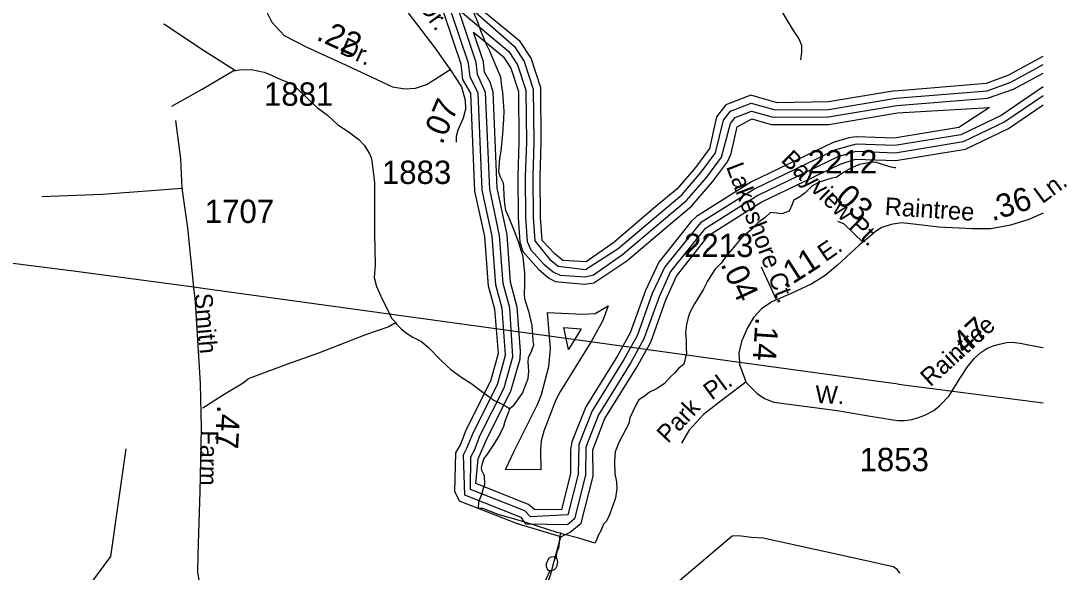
# Model space of a CAD drawing. Extents: x 2315291 to 2336543, y 597177 to 615230.
# Drawn here: x 2330575 to 2336179, y 606314 to 609266 of the extents above; entities that cross this region are included whole.
import ezdxf

# ---------------------------------------------------------------- set-up
doc = ezdxf.new("R2010")
doc.units = 0
for name, color, linetype in [('Exist Hydrographic Buffer Line', 7, 'Continuous'), ('Exist Hydrographic Creek Single Shore', 7, 'Continuous'), ('Exist Hydrographic Lake Shore', 7, 'Continuous'), ('Exist Hydrographic Misc Water Feature', 7, 'Continuous'), ('Exist Road Non-System Type 51', 7, 'Continuous'), ('Exist Road Non-System Type 51 Label', 7, 'Continuous'), ('Exist Road Secondary Mileage Hundredths English Label', 7, 'Continuous'), ('Exist Road Secondary Type 51 Attributed', 7, 'Continuous'), ('Exist Road Secondary Type 51 Label', 7, 'Continuous'), ('Exist Road Secondary Type 51 Number Label', 7, 'Continuous'), ('Exist Utilities Electrical Transmission Line', 7, 'Continuous')]:
    doc.layers.add(name, color=color, linetype=linetype)

msp = doc.modelspace()

# ---------------------------------------------------------------- linework, layer by layer
at = {"layer": 'Exist Hydrographic Buffer Line'}
for points in [[(2333503.2, 606568), (2333282.1, 606570.3), (2333254.4, 606606.8), (2332953.6, 606725.7), (2332945.2, 606941.9), (2332964.5, 606977.1), (2332998.9, 607063.3), (2333128.1, 607319.6), (2333171.2, 607476.6), (2333153.1, 607725.6), (2333118.9, 607852.7), (2333099.4, 608113.8), (2333046.1, 608359.9), (2333024.4, 608880.6), (2332981.1, 608965.3), (2332973.1, 609038.8), (2332835.9, 609447.4)], [(2332939.7, 609372.8), (2333218.3, 609128.4), (2333271.3, 609048.4), (2333319.4, 608900.7), (2333322.5, 608615.7), (2333316.4, 608432.6), (2333318.4, 608214.4), (2333327.4, 608087.6), (2333406.2, 607990.4), (2333452.1, 607952.3), (2333600, 607935.2), (2333774.4, 608046.9), (2333991.2, 608231.7), (2334115.2, 608335.1), (2334219, 608455.4), (2334294.7, 608559.2), (2334338.5, 608734.2), (2334376.3, 608782.8), (2334486.4, 608825.3), (2334615.4, 608788.7), (2334901.2, 608791.8), (2335261.5, 608852.3), (2335749.7, 608891.7), (2335876.6, 608938.3), (2336050.3, 609032.2)], [(2333304.9, 606610), (2333274.5, 606641.5), (2332982.7, 606757.2), (2332985, 606931), (2333003.9, 606966.9), (2333035.4, 607046.9), (2333164, 607301.6), (2333209.7, 607466.2), (2333193.1, 607728.9), (2333158.7, 607859.5), (2333139.2, 608116.8), (2333086.3, 608365), (2333064.4, 608882.3), (2333020.3, 608977.9), (2333012.9, 609043.1), (2332918.8, 609326.2), (2333188.2, 609101.3), (2333234.8, 609030.8), (2333279.7, 608894), (2333282.5, 608616.2), (2333276.4, 608433.9), (2333278.4, 608214), (2333287.7, 608084.7), (2333306.1, 608039), (2333376.9, 607963.1), (2333426.7, 607921.4), (2333463.4, 607904.4), (2333597.3, 607895.4), (2333642.4, 607905.9), (2333797.4, 608014.2), (2334017, 608201.1), (2334140.7, 608304.3), (2334249.1, 608429.3), (2334327.3, 608535.6), (2334375.5, 608716.5), (2334400.9, 608749.4), (2334488.4, 608783.1), (2334604.7, 608750.2), (2334901.6, 608751.8), (2335266.4, 608812.7), (2335753, 608851.8), (2335891, 608900.8), (2336050.3, 608986.8)], [(2333469.9, 606648.4), (2333325.8, 606649.9), (2333294.4, 606676.1), (2333011.9, 606788.7), (2333024.4, 606920.2), (2333071.9, 607030.5), (2333199.7, 607283.6), (2333248.5, 607455.9), (2333252, 607496.6), (2333232.9, 607732.1), (2333198.3, 607866.4), (2333179.2, 608119.8), (2333125.9, 608370.2), (2333104.3, 608884), (2333088.8, 608938.4), (2333059, 608990.5), (2333052.7, 609047.5), (2333000.2, 609204.8), (2333158.3, 609074.4), (2333198.5, 609013.3), (2333239.7, 608887.4), (2333242.5, 608616.6), (2333236.4, 608435.2), (2333238.4, 608213.6), (2333247.7, 608081.7), (2333263.5, 608030.4), (2333347.7, 607935.8), (2333401.5, 607890.4), (2333436.5, 607870.5), (2333594.6, 607855.5), (2333643.4, 607862.4), (2333820.4, 607981.5), (2334042.9, 608170.6), (2334166.5, 608273.6), (2334279.7, 608403.3), (2334359.5, 608512), (2334379.6, 608555.8), (2334412.4, 608699), (2334490.3, 608741), (2334593.6, 608711.8), (2334902.4, 608711.8), (2335271.1, 608772.9), (2335762.2, 608802.9), (2335598, 608694.9), (2335253.3, 608638.6), (2335049.7, 608645.8), (2335009.3, 608640.2), (2334926.2, 608613.9), (2334488.2, 608403.4), (2334194.2, 608218), (2334164.5, 608191.2), (2333992.4, 607974.2), (2333920, 607821.7), (2333838.6, 607595.7), (2333771, 607472.7), (2333600.8, 607199.3), (2333526.5, 607012.2), (2333518.5, 606969.2), (2333519.4, 606842.7), (2333469.9, 606648.4)], [(2336050.3, 608912), (2335825.4, 608759.9), (2335610.3, 608656.4), (2335255.7, 608598.5), (2335048.2, 608605.8), (2334938.1, 608575.8), (2334505.7, 608367.4), (2334215.7, 608184.2), (2334023.8, 607949.3), (2333956.5, 607805.4), (2333875.1, 607579.2), (2333805.4, 607452.4), (2333634.4, 607178.2), (2333563.7, 606997.9), (2333559.6, 606837.9), (2333504.2, 606621), (2333304.9, 606610)], [(2336050.3, 608863.9), (2335845.5, 608725), (2335622.2, 608617.8), (2335258.2, 608558.4), (2335047, 608565.8), (2334950.4, 608537.6), (2334522.9, 608331.4), (2334237, 608150.4), (2334055.2, 607924.5), (2333993, 607789), (2333912, 607562.7), (2333839.9, 607432.2), (2333668.4, 607157), (2333601.2, 606983.5), (2333599.5, 606833), (2333539.9, 606598.6), (2333503.2, 606568)], [(2333359.2, 606862.1), (2333171.4, 606862.9), (2333218.1, 606964.9), (2333342.4, 607211.6), (2333362.9, 607265.2), (2333402.9, 607414.5), (2333411.5, 607509.4), (2333395.7, 607704.8), (2333584.4, 607695.7), (2333651, 607699.4), (2333720.9, 607740.4), (2333692.4, 607661.7), (2333633, 607553.6), (2333464.6, 607283.9), (2333441, 607236.3), (2333376.9, 607069.6), (2333362.7, 607017.8), (2333358.4, 606969.2), (2333359.2, 606862.1)], [(2333508.3, 607505.5), (2333482.5, 607623.5), (2333576, 607616.2), (2333508.3, 607505.5)]]:
    msp.add_lwpolyline(points, dxfattribs=at)
at = {"layer": 'Exist Hydrographic Creek Single Shore'}
msp.add_lwpolyline([(2331553.5, 602566.1), (2331594.5, 602617), (2331766.4, 602893.1), (2332166.4, 603621.4), (2332288.4, 603905.2), (2332508.5, 604324.4), (2333168.2, 605058.9), (2333228.5, 605153.4), (2333244.6, 605266.1), (2333246.6, 605470.2), (2333248.1, 605841.5), (2333262.7, 605910.9), (2333411.5, 606298.5), (2333429.6, 606364.9), (2333467.8, 606503.8)], dxfattribs=at)
at = {"layer": 'Exist Hydrographic Lake Shore'}
for points in [[(2333467.8, 606503.8), (2333234.5, 606572.2), (2332924.5, 606694.2), (2332899.5, 606745.7), (2332905.4, 606952.7), (2332929.4, 606996.3), (2332962.4, 607079.7), (2333092.4, 607337.6), (2333132.4, 607486.9), (2333113.4, 607722.4), (2333079.5, 607845.8), (2333059.4, 608110.8), (2333006.5, 608354.8), (2332984.4, 608878.9), (2332942.3, 608952.7), (2332933.5, 609034.4), (2332795.5, 609442.3), (2332802.5, 609534.5), (2332819.5, 609558.1), (2332944.4, 609543.5)], [(2335256.6, 608892.1), (2334900.4, 608831.8), (2334626.4, 608827.2), (2334484.5, 608867.4), (2334351.5, 608816.1), (2334301.4, 608751.7), (2334262.5, 608582.8), (2334188.5, 608481.3), (2334089.4, 608365.8), (2333965.6, 608262.2), (2333751.5, 608079.7), (2333602.4, 607975.2), (2333477.5, 607983.3), (2333435.5, 608017.7), (2333367.4, 608090.5), (2333358.4, 608214.8), (2333356.3, 608431.3), (2333362.5, 608615.3), (2333359.4, 608907.2), (2333307.5, 609065.9), (2333248.5, 609155.4), (2332979.5, 609377.5)], [(2335256.6, 608892.1), (2335746.4, 608931.6), (2335862.5, 608975.7), (2336050.3, 609077.5)], [(2335260.7, 608518.3), (2335634.5, 608579.2), (2335865.6, 608690.3), (2336050.3, 608815.5)], [(2333467.8, 606503.8), (2333517.5, 606527.9), (2333575.5, 606576.1), (2333639.5, 606828.1), (2333638.5, 606969.2), (2333702.5, 607135.9), (2333874.5, 607411.9), (2333948.5, 607546.2), (2334029.5, 607772.6), (2334086.5, 607899.7), (2334258.4, 608116.7), (2334540.5, 608295.4), (2334962.5, 608499.5), (2335045.6, 608525.8), (2335260.7, 608518.3)]]:
    msp.add_lwpolyline(points, dxfattribs=at)
at = {"layer": 'Exist Hydrographic Misc Water Feature'}
for points in [[(2333194.4, 607187.6), (2333198.3, 607193.5), (2333217.9, 607210), (2333231.9, 607229.8), (2333261.6, 607272.4), (2333279, 607318.4), (2333292.4, 607350.4), (2333296.1, 607390.5), (2333294.2, 607414.7), (2333291.8, 607438.6), (2333293.6, 607462.6), (2333311, 607500.5), (2333322.7, 607530.8), (2333318.2, 607554.6), (2333313.3, 607634.4), (2333296.9, 607704.2), (2333276, 607770.2), (2333271.7, 607796), (2333275.1, 607859.9), (2333274.7, 607916), (2333269.8, 607965.8), (2333265.5, 608001.7), (2333238.6, 608087.7), (2333218.3, 608139.4), (2333189.2, 608214.7), (2333173.2, 608250.8), (2333166.5, 608286.7), (2333164.2, 608330.4), (2333161.8, 608376.6), (2333159.5, 608396.5), (2333142.9, 608432.2), (2333134.5, 608458.2), (2333140.2, 608530.4), (2333147.4, 608568.2), (2333156.2, 608660.5), (2333162, 608740.4), (2333163, 608782.4), (2333160.7, 608832.2), (2333156.2, 608884.4), (2333151.7, 608914.3), (2333145.1, 608964.3), (2333122.8, 609018), (2333087.7, 609103.6), (2333065.6, 609147), (2333038.7, 609212.7), (2333022.1, 609258.6), (2332978.8, 609366.1)], [(2331341.1, 609250.8), (2331558.7, 609104.9), (2331725.4, 609000.7)], [(2331383.7, 608809.2), (2331547, 608901), (2331711.4, 608998.7), (2331725.4, 609000.7)], [(2331725.4, 609000.7), (2331743.6, 609003.3), (2331809.6, 609005.9), (2331877.5, 608990.4), (2331921.4, 608972.9), (2331971.8, 608949.4), (2332028.2, 608928), (2332064.7, 608894.5), (2332112.9, 608849.2), (2332163.4, 608799.8), (2332217.9, 608760.3), (2332272.2, 608708.8), (2332328.8, 608673.5), (2332385.4, 608630.1), (2332415.8, 608598.4), (2332442.2, 608554.6), (2332453.9, 608529), (2332469.7, 608401.3), (2332468.7, 608127.3), (2332472.2, 607959.3), (2332467.4, 607891.5), (2332479.8, 607843.4), (2332512.6, 607771.9), (2332545.4, 607706.1), (2332559.5, 607674.4), (2332579.6, 607654.8), (2332581.7, 607650.8)], [(2335261.3, 608479.2), (2335253.7, 608479.2), (2335235.7, 608482.7), (2335195.5, 608494.5), (2335169, 608504.1), (2335155.1, 608509.8), (2335123.3, 608507.7), (2335067.5, 608497.1), (2335023.2, 608478.6), (2334985.9, 608458.3), (2334959.9, 608439.9), (2334942.2, 608427.9), (2334918, 608423.5), (2334884, 608413.2), (2334846.7, 608400.6), (2334811, 608380.4), (2334775.5, 608346), (2334747.6, 608323.8), (2334714, 608303.3), (2334706, 608283), (2334690.2, 608247.2), (2334650.4, 608232.6), (2334622.5, 608236.4), (2334590.4, 608239.9), (2334562.7, 608215.7), (2334522.7, 608185.2), (2334483.3, 608142.9), (2334451.5, 608118.5), (2334418.3, 608084.2), (2334382.4, 608041.7), (2334352.9, 608005.6), (2334325.2, 607969.2), (2334291.8, 607934.9), (2334252.6, 607872.7), (2334230.9, 607828.5), (2334205.5, 607788.1), (2334183.7, 607750), (2334158.1, 607703.6), (2334148.7, 607677.4), (2334140.7, 607639.3), (2334135.5, 607597.5), (2334137.8, 607555.4), (2334138.6, 607511.4), (2334140.7, 607485.6), (2334133.1, 607457.6), (2334125.5, 607427.5), (2334099.5, 607407), (2334077.7, 607381.1), (2334058, 607362.6), (2334036.1, 607340.3), (2334022.6, 607324.5), (2333982.8, 607298.1), (2333942.8, 607277.3), (2333913.1, 607255), (2333885.4, 607236.9), (2333871.6, 607215), (2333852.2, 607174.5), (2333836.4, 607140.5), (2333830.8, 607110.5), (2333813.2, 607076.2), (2333797.2, 607046.2), (2333778.1, 607007.7), (2333758.3, 606957.6), (2333755.2, 606905.7), (2333755.6, 606839.9), (2333766, 606797.8), (2333766.7, 606760), (2333759.5, 606711.6), (2333743.7, 606665.7), (2333724, 606611.5), (2333710.5, 606585.6), (2333696.5, 606571.4), (2333681.2, 606535.2), (2333665.4, 606506.8), (2333658, 606484.8), (2333649.8, 606469), (2333563.2, 606495.8), (2333479.2, 606516.9), (2333465.2, 606522.7)], [(2331549.2, 607193.8), (2331664.3, 607266.9), (2331765.3, 607327.9), (2331795.1, 607350.2), (2332004.4, 607428.7), (2332171.6, 607488.2), (2332422.3, 607587.2), (2332541.7, 607628.4), (2332581.7, 607650.8)], [(2332581.7, 607650.8), (2332587.6, 607641), (2332612, 607617), (2332640.1, 607593.4), (2332674.1, 607571.6), (2332720.5, 607548.4), (2332760.9, 607514.8), (2332819.7, 607455.2), (2332857.7, 607417.8), (2332878.4, 607398.2), (2332936.4, 607356.5), (2332985.2, 607325.3), (2333035.4, 607287.7), (2333069.7, 607264.3), (2333108.2, 607234.6), (2333146.2, 607217.1), (2333172.2, 607203.5), (2333184.1, 607195.6), (2333194.4, 607187.6)], [(2333465.2, 606522.7), (2333453.3, 606524.5), (2333330.9, 606563.2), (2333238.4, 606592.5), (2333132.2, 606623.1), (2333050.2, 606654.1), (2333026, 606654.1), (2333027.9, 606689.9), (2333045.3, 606736.4), (2333052.9, 606764.4), (2333060.5, 606784.3), (2333058.4, 606830.1), (2333043.8, 606858.2), (2333041.8, 606871.9), (2333047.5, 606896.1), (2333055.1, 606920.2), (2333070.7, 606940.5), (2333084.7, 606962.4), (2333110.5, 606998.6), (2333135.9, 607041.1), (2333161.5, 607095.2), (2333168.7, 607123.3), (2333184.7, 607163.5), (2333194.4, 607187.6)], [(2331137.9, 606973.4), (2331096.5, 606687.2), (2331055.9, 606396.9), (2330906.2, 606197.6), (2330770, 606020.2), (2330696.6, 605757.5), (2330592.7, 605410.6), (2330575.4, 605328.4), (2330556.2, 605266), (2330553.1, 605195.9), (2330551.6, 605144.3), (2330560.3, 605086.2), (2330564.8, 605034.4), (2330575.4, 604982.5), (2330583.6, 604940.7), (2330595.9, 604904.8), (2330596.3, 604886.9), (2330592.7, 604848.9), (2330557.4, 604752.5), (2330493.2, 604629.9), (2330403.4, 604428.9), (2330321.2, 604254.3), (2330246.9, 604099.6)], [(2335284.9, 606308.6), (2335280.8, 606312.4), (2335268.5, 606328), (2335248.8, 606342), (2335224.2, 606347.7), (2334957.8, 606406.8), (2334551, 606496.4), (2334489.1, 606499.6), (2334418.9, 606509), (2334384.9, 606506.8), (2334161, 606318.2), (2333830.4, 606037.1), (2333614.3, 605852.6), (2333402.5, 605866.3), (2333240.7, 605874.8)], [(2333465.2, 606522.7), (2333459.5, 606500.8), (2333457.8, 606470.7), (2333454.2, 606442.9), (2333446.6, 606422.5), (2333442.9, 606402.8), (2333442.7, 606388.6)], [(2333407.4, 606320.1), (2333403.5, 606320.3), (2333395.5, 606330), (2333391, 606342), (2333391, 606359.9), (2333396.7, 606376.1), (2333402.5, 606388.2), (2333415, 606396.4), (2333426.7, 606398.3), (2333432.4, 606396.6), (2333442.7, 606388.6)], [(2333442.7, 606388.6), (2333446.6, 606384.8), (2333449, 606366.5), (2333447.4, 606358.7), (2333443.5, 606342.7), (2333439.6, 606334.8), (2333429.3, 606324.5), (2333417.7, 606320.2), (2333407.4, 606320.1)], [(2333407.4, 606320.1), (2333388.1, 606278), (2333372.3, 606252), (2333364.8, 606219.9), (2333345.1, 606165.6), (2333323.5, 606115.4), (2333300.6, 606043.4), (2333281.3, 605989.1), (2333256.1, 605918.7), (2333242.5, 605880.6), (2333240.7, 605874.8)]]:
    msp.add_lwpolyline(points, dxfattribs=at)
at = {"layer": 'Exist Road Non-System Type 51'}
for points in [[(2333859.1, 610753.3), (2333871.9, 610668.6), (2333880.2, 610611.9), (2333895.2, 610572.7), (2334063.6, 610303.3), (2334625.4, 609357.4), (2334712.1, 609213.9), (2334742.1, 609170.6), (2334755.4, 609135.5), (2334755.4, 609097.2), (2334751, 609057.7)], [(2331439.6, 608370.6), (2331432, 608526.5), (2331405.4, 608731.9)], [(2330687, 608325), (2331012, 608338.3), (2331439.6, 608370.6)], [(2334458.7, 607330.6), (2334349.7, 607249.7), (2334231.3, 607158.2), (2334152.8, 607072.6), (2334112.7, 607004.2)]]:
    msp.add_lwpolyline(points, dxfattribs=at)
at = {"layer": 'Exist Road Secondary Type 51 Attributed'}
msp.add_line((2334622.2, 607771.9), (2334541.9, 607947.7), dxfattribs=at)
for points in [[(2331866.3, 609593.5), (2331953, 609631.8), (2332024.7, 609643.5), (2332084.7, 609638.5), (2332171.4, 609615.1), (2332373.1, 609521.7), (2332476.5, 609466.7), (2332554.9, 609423.3), (2332594.9, 609389.9), (2332653.2, 609304), (2332791.6, 609121.4), (2332860.2, 609025.7), (2332874.9, 609006.3)], [(2331883, 609329.9), (2331919.7, 609259.8), (2331984.7, 609188.1), (2332106.4, 609124.7), (2332313.1, 609031.3), (2332564.9, 608912.8), (2332631.5, 608902.8), (2332688.2, 608906.2), (2332748.2, 608924.5), (2332793.3, 608952.9), (2332874.9, 609006.3)], [(2332874.9, 609006.3), (2332935, 608912.8), (2332955, 608841.1), (2332956.6, 608792.7), (2332943.3, 608744.4), (2332915, 608681), (2332906.6, 608645.9), (2332906.6, 608615.9)], [(2331707.5, 605814.9), (2331641.9, 605953.7), (2331570.7, 606114.4), (2331540.3, 606203.8), (2331523.2, 606316), (2331525.1, 606405.4), (2331528.9, 606525.2), (2331534.6, 606745.7), (2331542.2, 607085.2), (2331537.2, 607323.8), (2331509.9, 607762.1), (2331502, 607839.9), (2331470, 608157.6), (2331439.6, 608370.6)], [(2336050.3, 608236.5), (2335973.8, 608202.4), (2335875.4, 608171.9), (2335769.9, 608152), (2335672.7, 608152), (2335492.2, 608161.9), (2335372.7, 608174.8), (2335291.8, 608184.2), (2335236.8, 608174.8), (2335186.4, 608159.6), (2335157.1, 608140.8), (2335112.6, 608103.3), (2335084.2, 608080.4)], [(2335084.2, 608080.4), (2334982.6, 608179.3), (2334950.5, 608192.2)], [(2335084.2, 608080.4), (2335064.5, 608064.6), (2334949.1, 607957.4), (2334882.9, 607902.2), (2334811.4, 607857.6), (2334701.2, 607806.1), (2334622.2, 607771.9)], [(2334622.2, 607771.9), (2334598.1, 607761.5), (2334541.9, 607724), (2334498.5, 607678.2), (2334466.9, 607622), (2334435.2, 607549.3), (2334421.2, 607488.3), (2334424, 607437), (2334424.7, 607425), (2334448.2, 607358.3), (2334458.7, 607330.6), (2334517.8, 607271.2), (2334557.5, 607243), (2334607.5, 607223.9)], [(2334607.5, 607223.9), (2334947.2, 607180), (2335114.1, 607150.2), (2335247.5, 607128.7), (2335275.5, 607126.6), (2335309.9, 607126.6), (2335346.4, 607130.9), (2335376.6, 607139.5), (2335417.4, 607154.5), (2335464.8, 607180.3), (2335497, 607206.1), (2335546.5, 607257.7), (2335604.6, 607350.2), (2335644.7, 607412.9), (2335683.3, 607459.4), (2335717.3, 607490), (2335749.1, 607511.6), (2335782, 607525.2), (2335816.1, 607535.4), (2335854.7, 607543.4), (2335885.3, 607546), (2335926.9, 607540.3), (2336035.7, 607519.4), (2336050.3, 607516.7)]]:
    msp.add_lwpolyline(points, dxfattribs=at)
at = {"layer": 'Exist Utilities Electrical Transmission Line'}
for p, q in [((2335273.5, 607320.2), (2334424, 607437)), ((2336050.3, 607219.6), (2335275.4, 607319.6))]:
    msp.add_line(p, q, dxfattribs=at)
for points in [[(2331502, 607839.9), (2330843.2, 607928.1), (2329978.4, 608036.7), (2329107.7, 608149.3), (2329014.6, 608160.7)], [(2334424, 607437), (2333818, 607520.3), (2331561.9, 607831.9), (2331502, 607839.9)]]:
    msp.add_lwpolyline(points, dxfattribs=at)

# ---------------------------------------------------------------- texts
at = {"layer": 'Exist Road Non-System Type 51 Label'}
for s, rotation, p in [('Pl.', 36.3694, (2334275.2, 607231.6)), ('Park', 46.7358, (2334040.6, 606999.4))]:
    msp.add_text(s, height=95, rotation=rotation, dxfattribs=at).set_placement(p)
at = {"layer": 'Exist Road Secondary Mileage Hundredths English Label'}
for s, rotation, p in [('.22', 335.8879, (2332151.6, 609167.2)), ('.07', 66.7023, (2332831.6, 608598.8)), ('.03', 316.2242, (2334896.9, 608344.6)), ('.36', 17.6177, (2335777.5, 608192.5)), ('.11', 32.7635, (2334669.9, 607828.4)), ('.04', 294.7397, (2334320.9, 607963.2)), ('.14', 266.0656, (2334510.5, 607681.5)), ('.47', 42.1779, (2335599.3, 607442)), ('.47', 266.5367, (2331627.5, 607210.3))]:
    msp.add_text(s, height=125, rotation=rotation, dxfattribs=at).set_placement(p)
at = {"layer": 'Exist Road Secondary Type 51 Label'}
for s, rotation, p in [('Dr.', 305.898, (2332701.8, 609342.3)), ('Dr.', 335.8879, (2332277.1, 609093.4)), ('Bayview Pt.', 315.8942, (2334641.7, 608515)), ('Lakeshore Ct.', 290.936, (2334351, 608485.2)), ('Ln.', 36.3699, (2336045.7, 608283.8)), ('Raintree', 356.2417, (2335199.9, 608226.8)), ('E.', 34.2749, (2334884, 607972.7)), ('Smith', 275.0239, (2331505, 607803.8)), ('Raintree', 42.2138, (2335445.9, 607302.9)), ('W.', 357.6201, (2334828.5, 607220.1)), ('Farm', 268.8552, (2331538.2, 607074.2))]:
    msp.add_text(s, height=95, rotation=rotation, dxfattribs=at).set_placement(p)
at = {"layer": 'Exist Road Secondary Type 51 Number Label'}
for s, p in [('1881', (2331876.9, 608811.4)), ('2212', (2334789.9, 608448.9)), ('1883', (2332508.5, 608392.6)), ('1707', (2331560, 608183.5)), ('2213', (2334126.9, 608001.6)), ('1853', (2335066.8, 606854.5))]:
    msp.add_text(s, height=125, dxfattribs=at).set_placement(p)

doc.saveas('drawing.dxf')
